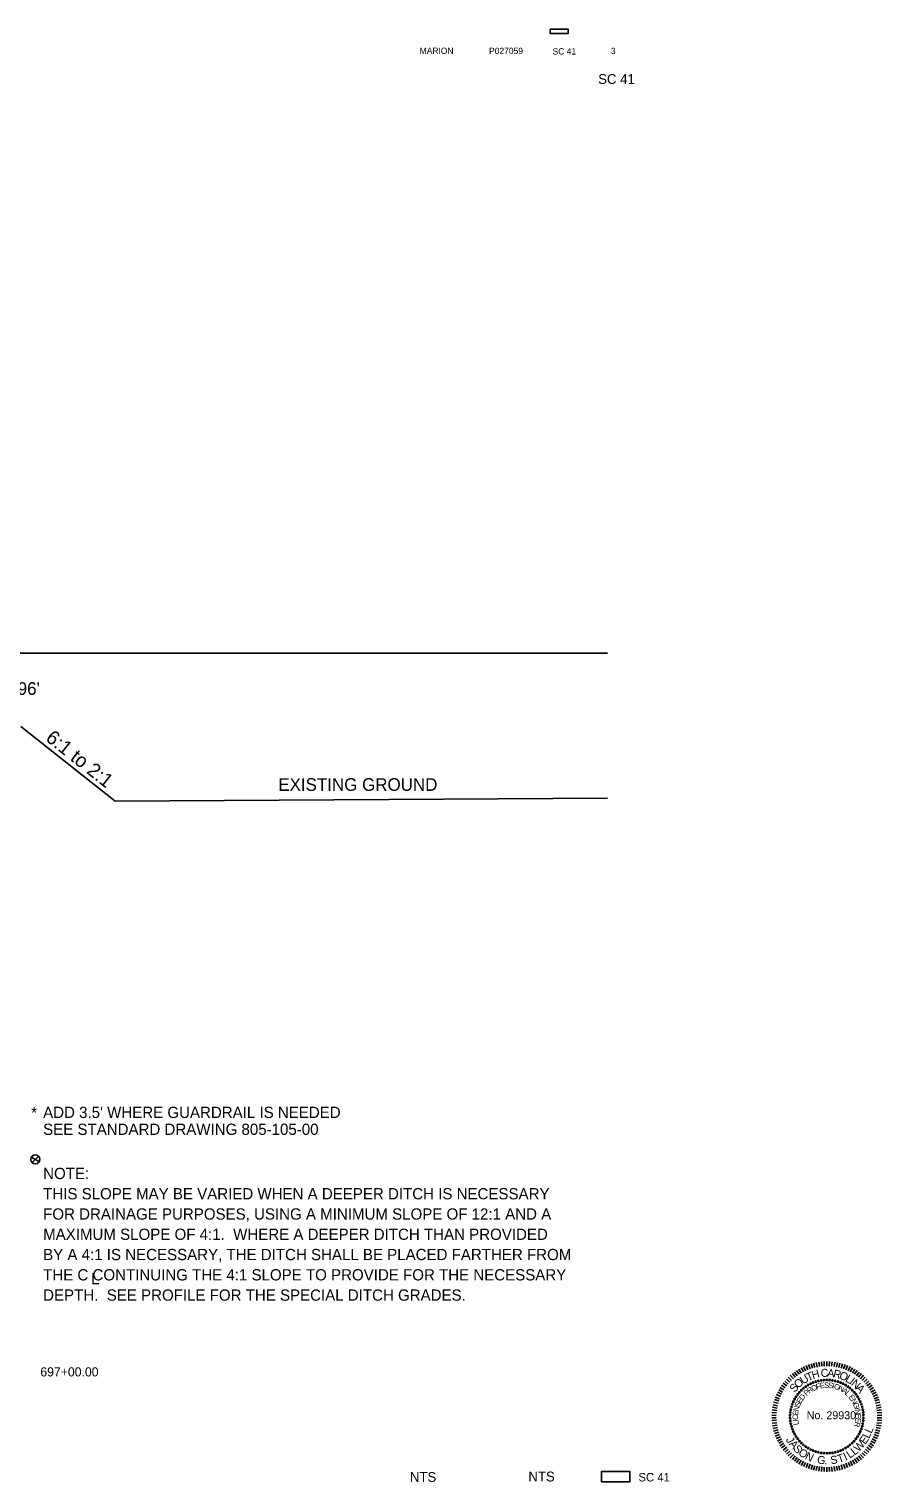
# Model space of a CAD drawing. Extents: x -8855 to -7045, y 42908 to 43943.
# Drawn here: x -7651 to -7045, y 42911 to 43943 of the extents above; entities that cross this region are included whole.
import ezdxf

# ---------------------------------------------------------------- set-up
doc = ezdxf.new("R2010")
doc.units = 0
for name, color, linetype in [('Default', 7, 'Continuous'), ('RD_EX_Misc', 7, 'Continuous'), ('RD_SHT_TX', 7, 'Continuous'), ('RD_TX_PEShield', 7, 'Continuous'), ('RD_TX_TypSect', 7, 'Continuous')]:
    doc.layers.add(name, color=color, linetype=linetype)

# ---------------------------------------------------------------- blocks, each defined once
blk = doc.blocks.new('STILLWELL')
at = {"layer": 'RD_TX_PEShield'}
for p, q in [((-19.7, 29.1), (-21.5, 31.8)), ((-18.2, 30), (-19.9, 32.8)), ((-16.7, 30.8), (-18.2, 33.7)), ((-15.1, 31.6), (-16.5, 34.6)), ((-13.6, 32.3), (-14.8, 35.3)), ((-11.9, 32.9), (-13, 36)), ((-10.3, 33.4), (-11.2, 36.6)), ((-8.6, 33.9), (-9.4, 37.1)), ((-6.9, 34.3), (-7.5, 37.5)), ((-5.2, 34.6), (-5.7, 37.8)), ((-3.5, 34.8), (-3.8, 38)), ((-1.8, 34.9), (-1.9, 38.2)), ((0, 34.9), (0, 38.2)), ((1.7, 34.9), (1.9, 38.2)), ((3.4, 34.8), (3.7, 38)), ((5.2, 34.6), (5.6, 37.8)), ((6.9, 34.3), (7.5, 37.5)), ((8.6, 33.9), (9.3, 37.1)), ((10.2, 33.4), (11.2, 36.6)), ((11.9, 32.9), (13, 36)), ((13.5, 32.3), (14.7, 35.3)), ((15.1, 31.6), (16.5, 34.6)), ((16.6, 30.8), (18.2, 33.7)), ((18.2, 30), (19.8, 32.8)), ((19.6, 29.1), (21.4, 31.8)), ((-29.5, 19.4), (-32.2, 21.3)), ((-28.5, 20.9), (-31.1, 22.8)), ((-27.4, 22.2), (-29.9, 24.3)), ((-26.3, 23.5), (-28.7, 25.7)), ((-25.1, 24.7), (-27.4, 27.1)), ((-23.8, 25.9), (-26, 28.4)), ((-22.5, 27), (-24.5, 29.6)), ((-21.1, 28.1), (-23, 30.7)), ((21.1, 28.1), (23, 30.7)), ((22.4, 27), (24.5, 29.6)), ((23.8, 25.9), (25.9, 28.4)), ((25, 24.7), (27.3, 27.1)), ((26.2, 23.5), (28.6, 25.7)), ((27.4, 22.2), (29.9, 24.3)), ((28.5, 20.9), (31.1, 22.8)), ((29.5, 19.4), (32.2, 21.3)), ((-34.1, 10.2), (-37.2, 11.2)), ((-33.6, 11.8), (-36.6, 12.9)), ((-32.9, 13.4), (-35.9, 14.7)), ((-32.2, 15), (-35.1, 16.4)), ((-31.4, 16.5), (-34.2, 18.1)), ((-30.5, 18), (-33.3, 19.7)), ((30.4, 18), (33.2, 19.7)), ((31.3, 16.5), (34.2, 18.1)), ((32.1, 15), (35.1, 16.4)), ((32.9, 13.4), (35.9, 14.7)), ((33.5, 11.8), (36.6, 12.9)), ((34.1, 10.2), (37.2, 11.2)), ((-35.9, -0.1), (-39.2, 0)), ((-35.8, 1.7), (-39.1, 1.9)), ((-35.6, 3.4), (-38.9, 3.8)), ((-35.4, 5.1), (-38.6, 5.7)), ((-35.1, 6.8), (-38.2, 7.5)), ((-34.6, 8.5), (-37.8, 9.4)), ((34.6, 8.5), (37.7, 9.4)), ((35, 6.8), (38.2, 7.5)), ((35.3, 5.1), (38.5, 5.7)), ((35.6, 3.4), (38.8, 3.8)), ((35.7, 1.7), (39, 1.9)), ((35.8, -0.1), (39.1, 0)), ((-35.9, -1.8), (-39.2, -1.9)), ((-35.8, -3.5), (-39.1, -3.8)), ((-35.6, -5.3), (-38.9, -5.6)), ((-35.4, -7), (-38.6, -7.5)), ((-35.1, -8.7), (-38.2, -9.4)), ((35, -8.7), (38.2, -9.4)), ((35.3, -7), (38.5, -7.5)), ((35.6, -5.3), (38.8, -5.6)), ((35.7, -3.5), (39, -3.8)), ((35.8, -1.8), (39.1, -1.9)), ((-34.6, -10.4), (-37.8, -11.2)), ((-34.1, -12), (-37.2, -13)), ((-33.6, -13.6), (-36.6, -14.8)), ((-32.9, -15.3), (-35.9, -16.6)), ((-32.2, -16.8), (-35.1, -18.3)), ((-31.4, -18.4), (-34.2, -19.9)), ((-30.5, -19.9), (-33.3, -21.6)), ((30.4, -19.9), (33.2, -21.6)), ((31.3, -18.4), (34.2, -19.9)), ((32.1, -16.8), (35.1, -18.3)), ((32.9, -15.3), (35.9, -16.6)), ((33.5, -13.6), (36.6, -14.8)), ((34.1, -12), (37.2, -13)), ((34.6, -10.4), (37.7, -11.2)), ((-29.5, -21.3), (-32.2, -23.2)), ((-28.5, -22.7), (-31.1, -24.7)), ((-27.4, -24.1), (-29.9, -26.2)), ((-26.3, -25.4), (-28.7, -27.6)), ((-25.1, -26.6), (-27.4, -28.9)), ((-23.8, -27.8), (-26, -30.2)), ((-22.5, -28.9), (-24.5, -31.4)), ((-21.1, -29.9), (-23, -32.6)), ((-19.7, -30.9), (-21.5, -33.7)), ((19.6, -30.9), (21.4, -33.7)), ((21.1, -29.9), (23, -32.6)), ((22.4, -28.9), (24.5, -31.4)), ((23.8, -27.8), (25.9, -30.2)), ((25, -26.6), (27.3, -28.9)), ((26.2, -25.4), (28.6, -27.6)), ((27.4, -24.1), (29.9, -26.2)), ((28.5, -22.7), (31.1, -24.7)), ((29.5, -21.3), (32.2, -23.2)), ((-18.2, -31.8), (-19.9, -34.7)), ((-16.7, -32.7), (-18.2, -35.6)), ((-15.1, -33.5), (-16.5, -36.4)), ((-13.6, -34.1), (-14.8, -37.2)), ((-11.9, -34.8), (-13, -37.8)), ((-10.3, -35.3), (-11.2, -38.4)), ((-8.6, -35.8), (-9.4, -38.9)), ((-6.9, -36.1), (-7.5, -39.3)), ((-5.2, -36.4), (-5.7, -39.7)), ((-3.5, -36.6), (-3.8, -39.9)), ((-1.8, -36.8), (-1.9, -40)), ((0, -36.8), (0, -40.1)), ((1.7, -36.8), (1.9, -40)), ((3.4, -36.6), (3.7, -39.9)), ((5.2, -36.4), (5.6, -39.7)), ((6.9, -36.1), (7.5, -39.3)), ((8.6, -35.8), (9.3, -38.9)), ((10.2, -35.3), (11.2, -38.4)), ((11.9, -34.8), (13, -37.8)), ((13.5, -34.1), (14.7, -37.2)), ((15.1, -33.5), (16.5, -36.4)), ((16.6, -32.7), (18.2, -35.6)), ((18.2, -31.8), (19.8, -34.7))]:
    blk.add_line(p, q, dxfattribs=at)
for centre in [(-15, 20.4), (-13.3, 21.5), (-11.6, 22.4), (-9.8, 23.2), (-7.9, 23.9), (-6, 24.4), (-4, 24.8), (-2, 25), (0, 25.1), (2, 25), (3.9, 24.8), (5.9, 24.4), (7.8, 23.9), (9.7, 23.2), (11.5, 22.4), (13.3, 21.5), (15, 20.4), (-22.9, 11.5), (-21.9, 13.2), (-20.7, 14.9), (-19.5, 16.4), (-18.1, 17.8), (-16.6, 19.2), (16.5, 19.2), (18, 17.8), (19.4, 16.4), (20.7, 14.9), (21.8, 13.2), (22.9, 11.5), (-26.1, 0.1), (-25.9, 2.1), (-25.6, 4), (-25.1, 6), (-24.5, 7.9), (-23.8, 9.7), (23.7, 9.7), (24.5, 7.9), (25.1, 6), (25.5, 4), (25.8, 2.1), (26, 0.1), (-26.1, -1.9), (-25.9, -3.9), (-25.6, -5.9), (-25.1, -7.8), (-24.5, -9.7), (24.5, -9.7), (25.1, -7.8), (25.5, -5.9), (25.8, -3.9), (26, -1.9), (-23.8, -11.6), (-22.9, -13.4), (-21.9, -15.1), (-20.7, -16.7), (-19.5, -18.3), (-18.1, -19.7), (-16.6, -21), (16.5, -21), (18, -19.7), (19.4, -18.3), (20.7, -16.7), (21.8, -15.1), (22.9, -13.4), (23.7, -11.6), (-15, -22.2), (-13.3, -23.3), (-11.6, -24.3), (-9.8, -25.1), (-7.9, -25.8), (-6, -26.3), (-4, -26.7), (-2, -26.9), (0, -27), (2, -26.9), (3.9, -26.7), (5.9, -26.3), (7.8, -25.8), (9.7, -25.1), (11.5, -24.3), (13.3, -23.3), (15, -22.2)]:
    blk.add_circle(centre, 0.49, dxfattribs=at)
for s, height, rotation, p in [('T', 5.68, 23.5044, (-13.2, 24.1)), ('H', 5.68, 16.1357, (-9.9, 25.6)), ('C', 5.68, 4.076, (-4.2, 27.1)), ('A', 5.68, 355.3651, (0.1, 27.4)), ('R', 5.68, 347.3188, (4.1, 27.1)), ('S', 5.68, 49.6435, (-22.9, 15.8)), ('O', 5.68, 41.5972, (-20.4, 18.8)), ('U', 5.68, 32.2152, (-16.9, 21.8)), ('O', 3.92, 24.9735, (-10, 16.9)), ('F', 3.92, 15.9995, (-7.1, 18.3)), ('E', 3.92, 8.9511, (-4.7, 19)), ('S', 3.92, 1.2546, (-1.9, 19.4)), ('S', 3.92, 353.558, (0.8, 19.5)), ('I', 3.92, 345.8615, (3.5, 19.2)), ('O', 3.92, 342.6583, (4.7, 19)), ('N', 3.92, 333.6842, (7.7, 18)), ('O', 5.68, 338.6079, (8.3, 26.2)), ('L', 5.68, 329.226, (12.6, 24.4)), ('I', 5.68, 322.5218, (15.5, 22.8)), ('N', 5.68, 319.1729, (16.8, 21.8)), ('A', 5.68, 310.4621, (20.1, 19)), ('E', 3.92, 60.2341, (-18.5, 7.9)), ('D', 3.92, 52.5376, (-17.1, 10.3)), ('P', 3.92, 41.0022, (-14.5, 13.5)), ('R', 3.92, 33.3057, (-12.5, 15.3)), ('A', 3.92, 325.3521, (10.4, 16.7)), ('L', 3.92, 317.6555, (12.6, 15.1)), ('E', 3.92, 308.0396, (15.1, 12.8)), ('N', 3.92, 300.343, (16.8, 10.6)), ('C', 3.92, 92.2915, (-20.4, -3.2)), ('E', 3.92, 83.9594, (-20.5, -0.2)), ('N', 3.92, 76.2628, (-20.2, 2.5)), ('S', 3.92, 67.9307, (-19.5, 5.4)), ('G', 3.92, 292.0109, (18.3, 8.1)), ('I', 3.92, 283.0368, (19.5, 5.1)), ('N', 3.92, 279.8336, (19.8, 4)), ('E', 3.92, 271.5014, (20.3, 1.1)), ('I', 3.92, 95.4947, (-20.2, -4.3)), ('L', 3.92, 101.9075, (-19.7, -6.6)), ('R', 3.92, 256.1083, (20.1, -4.4)), ('E', 3.92, 263.8049, (20.4, -1.7)), ('L', 5.68, 65.098, (31.6, -13.3)), ('J', 5.68, 299.033, (-29.4, -17.3)), ('A', 5.68, 310.5887, (-27.2, -20.6)), ('W', 5.68, 47.0518, (22.6, -26.4)), ('E', 5.68, 56.4327, (27.3, -21.1)), ('L', 5.68, 65.098, (30, -16.9)), ('S', 5.68, 310.5887, (-24.3, -24)), ('O', 5.68, 321.0072, (-20.8, -27.4)), ('N', 5.68, 333.4326, (-16, -30.8)), ('G', 5.68, 352.2045, (-7.2, -34.2)), ('S', 5.68, 8.0826, (2.9, -34.8)), ('T', 5.68, 18.9019, (8.5, -33.9)), ('I', 5.68, 25.3991, (13.3, -32.2)), ('L', 5.68, 34.0644, (16.2, -30.9)), ('L', 5.68, 37.6708, (19.6, -28.7)), ('.', 5.68, 0.8698, (-1.8, -34.9))]:
    blk.add_text(s, height=height, rotation=rotation, dxfattribs=at).set_placement(p)
blk.add_text('No. 29930', height=5.68, dxfattribs=at).set_placement((-14.3, -2.8))

msp = doc.modelspace()

# ---------------------------------------------------------------- linework, layer by layer
at = {"layer": 'Default'}
for p, q in [((-7849.3, 43499.3), (-7239.8, 43499.3)), ((-7656.4, 43447.2), (-7589.4, 43394.1)), ((-7589.4, 43394.1), (-7239.8, 43396.2))]:
    msp.add_line(p, q, dxfattribs=at)
at = {"layer": 'RD_EX_Misc'}
msp.add_lwpolyline([(-7244, 42910.6), (-7224, 42910.6), (-7224, 42918), (-7244, 42918)], close=True, dxfattribs=at)
at = {"layer": 'RD_SHT_TX'}
msp.add_lwpolyline([(-7280.5, 43942.7), (-7267.8, 43942.7), (-7267.8, 43939.5), (-7280.5, 43939.5)], close=True, dxfattribs=at)
at = {"layer": 'RD_TX_TypSect'}
for p, q in [((-7649.1, 43141.2), (-7643.4, 43138.2)), ((-7648.4, 43137.5), (-7644, 43142))]:
    msp.add_line(p, q, dxfattribs=at)
msp.add_circle((-7646.2, 43139.7), 3.2, dxfattribs=at)

# ---------------------------------------------------------------- block references
at = {"layer": 'Default'}
msp.add_blockref('STILLWELL', (-7084, 42957.9), dxfattribs=at)

# ---------------------------------------------------------------- texts
at = {"layer": 'RD_EX_Misc'}
for s, height, p in [("0.96'", 9, (-7668.7, 43469.7)), ('EXISTING GROUND ', 9, (-7473.6, 43401.5)), ('NTS', 7, (-7380.1, 42910.6)), ('NTS', 7, (-7296, 42910.9)), ('SC 41', 6, (-7217.8, 42910.9))]:
    msp.add_text(s, height=height, dxfattribs=at).set_placement(p)
msp.add_text('6:1 to 2:1', height=10, rotation=321.5624, dxfattribs=at).set_placement((-7639.5, 43437.7))
at = {"layer": 'RD_SHT_TX'}
for s, p in [('MARION', (-7373.2, 43925)), ('P027059', (-7323.9, 43924.9)), ('SC 41', (-7278.8, 43924.6)), ('3', (-7237.4, 43924.9))]:
    msp.add_text(s, height=4.5, rotation=0.0746, dxfattribs=at).set_placement(p)
msp.add_text('697+00.00', height=6.5, dxfattribs=at).set_placement((-7642.6, 42985.5))
at = {"layer": 'RD_TX_TypSect'}
for s, height, p in [('SC 41', 7, (-7246.4, 43903.7)), ('*', 8, (-7649.1, 43168.9)), ("ADD 3.5' WHERE GUARDRAIL IS NEEDED", 8, (-7640.6, 43169.1)), ('SEE STANDARD DRAWING 805-105-00', 8, (-7640.6, 43157.1)), ('NOTE:', 8, (-7640.6, 43125.7)), ('THIS SLOPE MAY BE VARIED WHEN A DEEPER DITCH IS NECESSARY', 8, (-7640.6, 43111.3)), ('FOR DRAINAGE PURPOSES, USING A MINIMUM SLOPE OF 12:1 AND A', 8, (-7640.6, 43096.9)), ('MAXIMUM SLOPE OF 4:1.  WHERE A DEEPER DITCH THAN PROVIDED', 8, (-7640.6, 43082.5)), ('BY A 4:1 IS NECESSARY, THE DITCH SHALL BE PLACED FARTHER FROM', 8, (-7640.6, 43068.1)), ('THE C CONTINUING THE 4:1 SLOPE TO PROVIDE FOR THE NECESSARY', 8, (-7640.6, 43053.7)), ('L', 8, (-7606.6, 43050.9)), ('DEPTH.  SEE PROFILE FOR THE SPECIAL DITCH GRADES.', 8, (-7640.6, 43039.3))]:
    msp.add_text(s, height=height, dxfattribs=at).set_placement(p)

doc.saveas('drawing.dxf')
